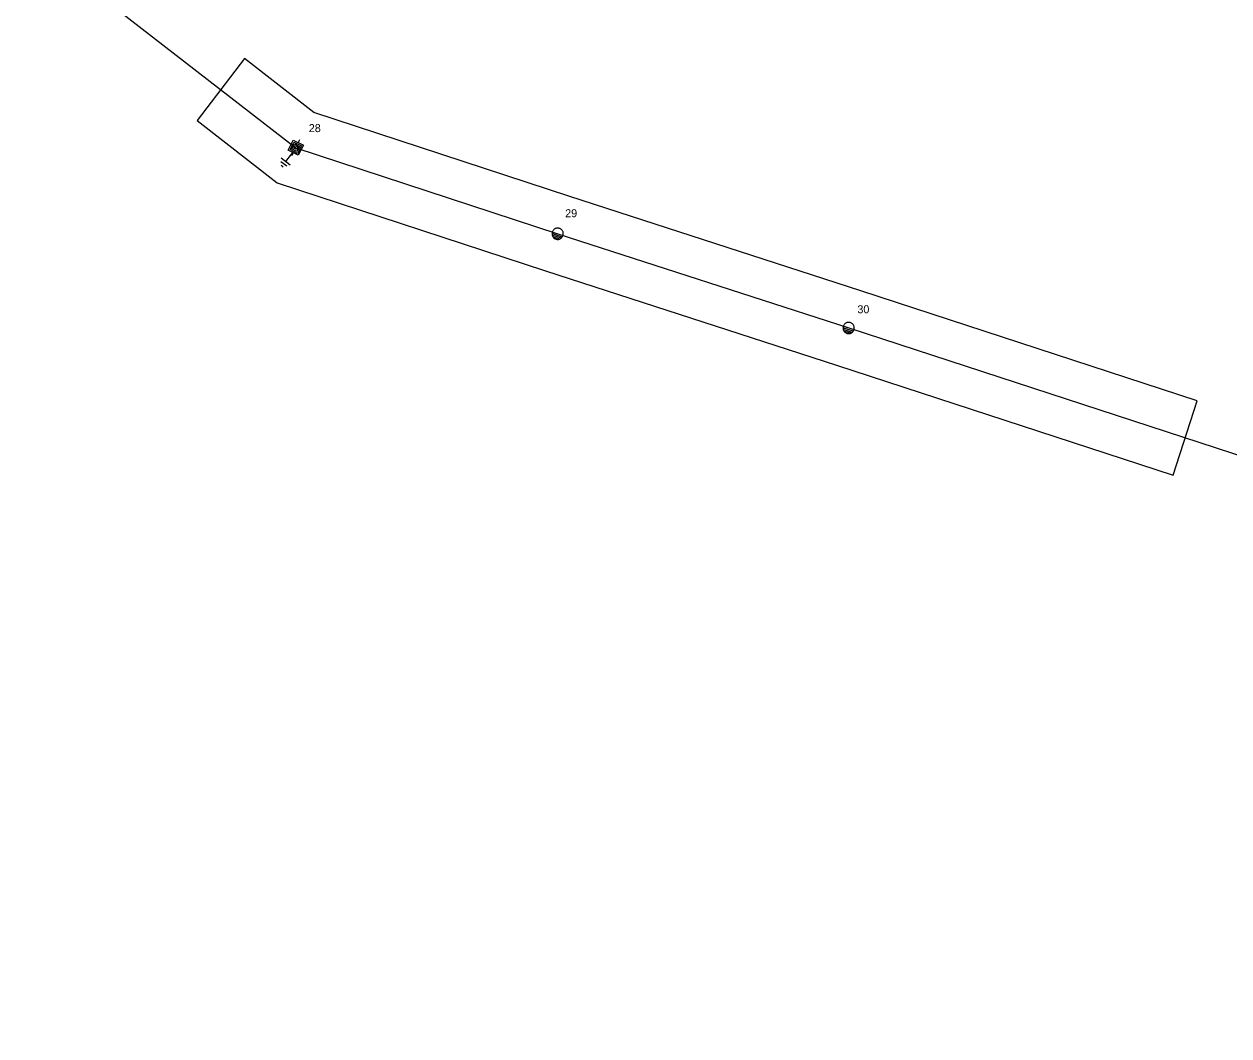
# Model space of a CAD drawing. Extents: x -761250 to -760338, y -1155000 to -1154503.
# Drawn here: x -760993.1 to -760731.1, y -1155000 to -1154780 of the extents above; entities that cross this region are included whole.
import ezdxf

# ---------------------------------------------------------------- set-up
doc = ezdxf.new("R2010")
doc.units = 0
for name, color, linetype in [('Vrstva 1', 7, 'Continuous'), ('Vrstva 13', 7, 'Continuous'), ('Vrstva 14', 7, 'Continuous'), ('Vrstva 15', 7, 'Continuous'), ('Vrstva 35', 7, 'Continuous')]:
    doc.layers.add(name, color=color, linetype=linetype)

msp = doc.modelspace()

# ---------------------------------------------------------------- linework, layer by layer
at = {"layer": 'Vrstva 1'}
msp.add_lwpolyline([(-761250, -1154560.04), (-761239.44, -1154568.33), (-761186.98, -1154609.48), (-761124.95, -1154658.28), (-761056.6, -1154711.35), (-760986.69, -1154766.03), (-760934.04, -1154806.89), (-760877.08, -1154825.6), (-760813.81, -1154846.09), (-760723.01, -1154875.68), (-760629.06, -1154906.1), (-760533.78, -1154936.84), (-760468.16, -1154958.01), (-760403.99, -1154978.73), (-760337.85, -1155000)], dxfattribs=at)
at = {"layer": 'Vrstva 13'}
for points in [[(-760935.694, -1154807.431), (-760934.579, -1154805.242)], [(-760935.29, -1154807.314), (-760934.454, -1154805.672)], [(-760934.868, -1154807.163), (-760934.31, -1154806.068)], [(-760933.774, -1154807.72), (-760934.868, -1154807.163)], [(-760934.579, -1154805.242), (-760932.39, -1154806.357)], [(-760934.454, -1154805.672), (-760932.812, -1154806.509)], [(-760934.438, -1154806.994), (-760934.159, -1154806.447)], [(-760933.891, -1154807.273), (-760934.438, -1154806.994)], [(-760934.31, -1154806.068), (-760933.216, -1154806.626)], [(-760934.159, -1154806.447), (-760933.612, -1154806.726)], [(-760933.612, -1154806.726), (-760933.891, -1154807.273)], [(-760933.216, -1154806.626), (-760933.774, -1154807.72)], [(-760932.812, -1154806.509), (-760933.648, -1154808.15)], [(-760932.39, -1154806.357), (-760933.506, -1154808.546)], [(-760933.484, -1154805.8), (-760933.145, -1154805.133)], [(-760933.506, -1154808.546), (-760935.694, -1154807.431)], [(-760933.648, -1154808.15), (-760935.29, -1154807.314)], [(-760934.6, -1154807.989), (-760934.94, -1154808.655)], [(-760875.915, -1154825.96), (-760875.884, -1154825.835), (-760875.866, -1154825.708), (-760875.862, -1154825.579), (-760875.87, -1154825.451), (-760875.893, -1154825.324), (-760875.928, -1154825.201), (-760875.976, -1154825.081), (-760876.036, -1154824.968), (-760876.108, -1154824.861), (-760876.191, -1154824.763), (-760876.284, -1154824.673), (-760876.385, -1154824.594), (-760876.494, -1154824.526), (-760876.61, -1154824.47), (-760876.731, -1154824.426), (-760876.855, -1154824.395), (-760876.983, -1154824.377), (-760877.111, -1154824.372), (-760877.239, -1154824.381), (-760877.366, -1154824.403), (-760877.489, -1154824.439), (-760877.609, -1154824.487), (-760877.722, -1154824.548), (-760877.829, -1154824.62), (-760877.927, -1154824.702), (-760878.016, -1154824.794), (-760878.096, -1154824.896), (-760878.164, -1154825.005), (-760878.22, -1154825.12), (-760878.264, -1154825.241), (-760878.296, -1154825.366), (-760878.313, -1154825.493), (-760878.318, -1154825.622), (-760878.309, -1154825.751), (-760878.286, -1154825.877), (-760878.251, -1154826), (-760878.203, -1154826.119), (-760878.143, -1154826.233), (-760878.071, -1154826.34), (-760877.988, -1154826.438), (-760877.895, -1154826.528), (-760877.794, -1154826.607), (-760877.685, -1154826.675), (-760877.569, -1154826.731), (-760877.449, -1154826.775), (-760877.324, -1154826.806), (-760877.197, -1154826.824), (-760877.068, -1154826.829), (-760876.94, -1154826.82), (-760876.813, -1154826.798), (-760876.689, -1154826.762), (-760876.57, -1154826.714), (-760876.457, -1154826.653), (-760876.35, -1154826.581), (-760876.252, -1154826.499), (-760876.163, -1154826.407), (-760876.084, -1154826.305), (-760876.015, -1154826.196), (-760875.959, -1154826.081), (-760875.915, -1154825.96)], [(-760878.311, -1154825.58), (-760876.127, -1154826.248)], [(-760878.265, -1154825.233), (-760875.916, -1154825.951)], [(-760878.23, -1154825.906), (-760876.34, -1154826.484)], [(-760878.057, -1154826.26), (-760876.699, -1154826.675)], [(-760812.645, -1154846.45), (-760812.614, -1154846.325), (-760812.596, -1154846.198), (-760812.592, -1154846.069), (-760812.6, -1154845.941), (-760812.623, -1154845.814), (-760812.658, -1154845.691), (-760812.706, -1154845.571), (-760812.766, -1154845.458), (-760812.838, -1154845.351), (-760812.921, -1154845.252), (-760813.014, -1154845.163), (-760813.115, -1154845.084), (-760813.224, -1154845.016), (-760813.34, -1154844.96), (-760813.461, -1154844.916), (-760813.585, -1154844.885), (-760813.713, -1154844.867), (-760813.841, -1154844.862), (-760813.969, -1154844.871), (-760814.096, -1154844.893), (-760814.219, -1154844.929), (-760814.339, -1154844.977), (-760814.452, -1154845.038), (-760814.559, -1154845.11), (-760814.657, -1154845.192), (-760814.746, -1154845.284), (-760814.826, -1154845.386), (-760814.894, -1154845.495), (-760814.95, -1154845.61), (-760814.994, -1154845.731), (-760815.026, -1154845.856), (-760815.043, -1154845.983), (-760815.048, -1154846.112), (-760815.039, -1154846.241), (-760815.016, -1154846.367), (-760814.981, -1154846.49), (-760814.933, -1154846.609), (-760814.873, -1154846.723), (-760814.801, -1154846.83), (-760814.718, -1154846.928), (-760814.625, -1154847.018), (-760814.524, -1154847.097), (-760814.415, -1154847.165), (-760814.299, -1154847.221), (-760814.179, -1154847.265), (-760814.054, -1154847.296), (-760813.927, -1154847.314), (-760813.798, -1154847.319), (-760813.67, -1154847.31), (-760813.543, -1154847.288), (-760813.419, -1154847.252), (-760813.3, -1154847.204), (-760813.187, -1154847.143), (-760813.08, -1154847.071), (-760812.982, -1154846.989), (-760812.893, -1154846.897), (-760812.814, -1154846.795), (-760812.745, -1154846.686), (-760812.689, -1154846.571), (-760812.645, -1154846.45)], [(-760815.041, -1154846.07), (-760812.857, -1154846.738)], [(-760814.995, -1154845.723), (-760812.646, -1154846.441)], [(-760814.96, -1154846.396), (-760813.07, -1154846.974)], [(-760814.787, -1154846.75), (-760813.429, -1154847.165)]]:
    msp.add_lwpolyline(points, dxfattribs=at)
at = {"layer": 'Vrstva 15'}
for points in [[(-760935.228, -1154810.658), (-760937.251, -1154809.189)], [(-760934.77, -1154807.901), (-760936.24, -1154809.923)], [(-760935.983, -1154810.876), (-760937.257, -1154809.951)], [(-760936.974, -1154810.935), (-760937.181, -1154810.784)], [(-760936.759, -1154811.091), (-760936.974, -1154810.935)]]:
    msp.add_lwpolyline(points, dxfattribs=at)
at = {"layer": 'Vrstva 35'}
msp.add_lwpolyline([(-760738.02, -1154861.93), (-760811.18, -1154838.01), (-760874.44, -1154817.52), (-760930.08, -1154799.24), (-760945.19, -1154787.48), (-760955.49, -1154801), (-760938.09, -1154814.51), (-760879.72, -1154833.68), (-760816.44, -1154854.17), (-760743.29, -1154878.09)], close=True, dxfattribs=at)

# ---------------------------------------------------------------- texts
at = {"layer": 'Vrstva 14'}
for s, p in [('28', (-760931.2, -1154803.5)), ('29', (-760875.45, -1154822.01)), ('30', (-760811.91, -1154842.89))]:
    msp.add_text(s, height=1.74, dxfattribs=at).set_placement(p)

doc.saveas('drawing.dxf')
